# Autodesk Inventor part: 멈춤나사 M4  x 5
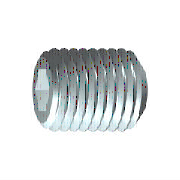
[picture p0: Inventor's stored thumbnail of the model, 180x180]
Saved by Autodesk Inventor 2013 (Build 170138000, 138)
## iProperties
IsCustomPart: 1
Created: 2012-02
Part Number: 멈춤나사 M4  x 5
Material: 강철, 연강
Description: 6각 소켓 머리 없는 멈춤 나사
Document SubType Name: Modeling
Standard: KS B 1028
Designer: mduedu
Standards Organization: KS
Language: ko-KR
Size Designation: 납작점M4x5
Categories: <MemberInstance><Categories><Category DisplayName="조임쇠" InternalName="e4da775c-781d-43d5-af7c-5136215cf5a6" Mnemonic="FSTN"><Category DisplayName="볼트" InternalN
Density: 1 g/cm^3
Author: mduedu
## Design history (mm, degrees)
sketch "스케치1"
  geometry: L1 (0, 0)-(1.833, 0); L2 (5, 1.155)-(5, 2); L3 (5, 2)-(0, 2); L4 (5, 1.155)-(2.5, 1.155); L5 (2.5, 1.155)-(1.833, 0); L6 (0, -0.4)-(0, 2.4) reference; L7 (0, 2)-(0, 0)
  constraints: 13 end point, 3 parallel, 1 collinear, 1 perpendicular, 1 point on line
  dimensions: "d0" = 2.5 distance of L2.start L4.end (= INTI); "d1" = 60 deg angle of L5 L1; "d2" = 4 diameter of L3 L1 (= NND); "d3" = 2.3094 diameter of L4 L1 (= 1.1547 x SW); "d5" = 5 distance from line of L2 L3.end (= NLG)
revolve "본체" sketch "스케치1" stored, may be unused: angle "d6" = 90 deg
sketch "스케치2"
  geometry: L1 (-0.577, 1)-(0.577, 1); L2 (0.577, 1)-(1.155, 0); L3 (1.155, 0)-(0.577, -1); L4 (0.577, -1)-(-0.577, -1); L5 (-0.577, -1)-(-1.155, 0); L6 (-1.155, 0)-(-0.577, 1); A1 r 1.155 centre (0, 0) between (-0.577, 1) and (0.577, 1) reference; 2 further points
  constraints: 12 end point, 2 point on circle, 1 coincident, 1 horizontal, 11 other
extrude "슬롯" join sketch "스케치2" taper "d9" = 0 deg; stored distance "d21" = 10
workaxis "Work Axis1"
workplane "Work Plane1"
body "Solid1"
chamfer "모따기1" distance "d7" = 0.42941 (= -0.5 x GD1 + 0.5 x NND); stored, may be unused: angle "d8" = 45 deg (= FAWI), second distance "d29" = 0.42941 (= -0.5 x GD1 + 0.5 x NND)
feature "스레드" dims "d11" = 5 (= NLG), "d12" = 0
chamfer "모따기2" distance "d13" = 0.42941 (= -0.5 x GD1 + 0.5 x NND); stored, may be unused: angle "d14" = 45 deg (= FAWI), second distance "d30" = 0.42941 (= -0.5 x GD1 + 0.5 x NND)
other parameters: "NND" = 4 [user parameter; used in 5 equation terms], "NLG" = 5 [user parameter; used in 2 equation terms], "INTI" = 2.5 [user parameter; used in 1 equation term], "FAWI" = 45 deg [user parameter; used in 2 equation terms], "SW" = 2 [user parameter; used in 2 equation terms], "GD1" = 3.14117 (= THREADDIA - 1.2269 x PTC) [user parameter; used in 4 equation terms], "d4" = 0, "FAWI1" = 45 deg [user parameter], "d15" = 0, "d31" = 0, "GUL" = 0.42941 (= 0.61345 x PTC) [user parameter], "SPD" = 2.5 [user parameter], "TPU" = 14.28571 (computed from PTC) [user parameter], "TOA" = 30 deg [user parameter], "THREADDIA" = 4 [user parameter; used in 1 equation term], "PTC" = 0.7 [user parameter; used in 4 equation terms], "GAL" = 0.42941 (= 0.61345 x PTC) [user parameter], "E0" = 2.31 (= 1.155 x SW) [user parameter]
